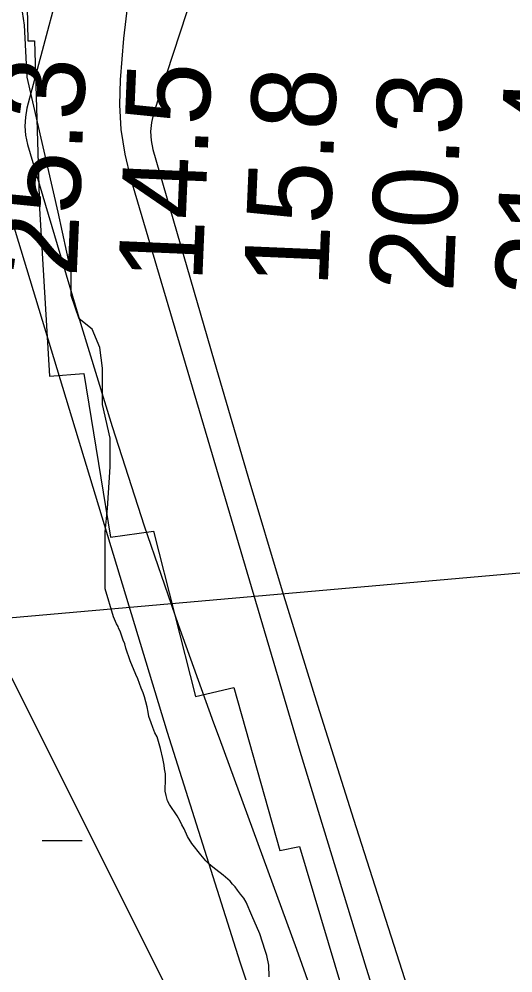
# Model space of a CAD drawing. Extents: x 3281947 to 3319794, y 715894 to 741249.
# Drawn here: x 3294621 to 3295014, y 730771 to 731530 of the extents above; entities that cross this region are included whole.
import ezdxf

# ---------------------------------------------------------------- set-up
doc = ezdxf.new("R2010")
doc.units = 0
for name, color, linetype in [('V-RIVR-RANG', 7, 'Continuous'), ('V-RRAP-RVMT', 7, 'Continuous'), ('V-SITE-VEGE', 7, 'Continuous'), ('V-TOPO-MAJR', 7, 'Continuous'), ('V-TOPO-MINR', 7, 'Continuous'), ('V-WETL-SWMP', 7, 'Continuous')]:
    doc.layers.add(name, color=color, linetype=linetype)

msp = doc.modelspace()

# ---------------------------------------------------------------- linework, layer by layer
at = {"layer": 'V-RIVR-RANG'}
msp.add_line((3294266.87, 731023.3), (3295442.35, 731126.59), dxfattribs=at)
at = {"layer": 'V-RRAP-RVMT'}
for points in [[(3294916.96, 732419.73), (3294695.42, 732452.11), (3294671.83, 732315.84), (3294667.42, 732316.1), (3294647.19, 732175.26), (3294649.39, 732174.71), (3294634, 732052.32), (3294626.51, 732052.13), (3294612.34, 731919.29), (3294603.81, 731919.44), (3294591.01, 731780.63), (3294593.83, 731648.32), (3294624.8, 731648.66), (3294627.58, 731512.85), (3294632.84, 731512.67), (3294636.8, 731379.25), (3294644.88, 731245.94), (3294672.26, 731248.07)], [(3294672.26, 731248.07), (3294693.46, 731117.69), (3294727.56, 731122.49), (3294761.16, 730990.85), (3294791.42, 730997.99), (3294828.28, 730868.41), (3294843.88, 730871.62), (3294883.31, 730739.23)]]:
    msp.add_lwpolyline(points, dxfattribs=at)
at = {"layer": 'V-SITE-VEGE'}
for points in [[(3294774.73, 730854.96), (3294771.77, 730857.84), (3294769.33, 730860), (3294765.16, 730864.84), (3294758.23, 730873.96), (3294754.79, 730879.49), (3294751.88, 730885.72), (3294750.16, 730888.76), (3294748.8, 730891.78), (3294746.56, 730895.88), (3294740.34, 730904.99), (3294738.8, 730907.85), (3294737.63, 730912.11), (3294736.97, 730915.47), (3294737.13, 730925.55), (3294737.02, 730929.44), (3294736.37, 730933.33), (3294736.07, 730936.34), (3294735.08, 730941.48), (3294733.27, 730949.64), (3294730.41, 730958.7), (3294728.69, 730962.09), (3294727.17, 730966.35), (3294725.64, 730969.91), (3294723.95, 730975.06), (3294723.47, 730978.43), (3294722.66, 730982.69), (3294720.48, 730990.67), (3294719.3, 730993.87), (3294717.77, 730997.61), (3294716.58, 731001.16), (3294715.05, 731005.07), (3294713.52, 731008.46), (3294708.92, 731019.31), (3294705.54, 731029.44), (3294704.71, 731032.81), (3294703.34, 731035.83), (3294702.51, 731038.85), (3294701.32, 731042.05), (3294699.79, 731045.61), (3294699.45, 731046.68), (3294698.25, 731048.81), (3294695.7, 731054.4), (3294689.02, 731076.55), (3294689.02, 731122.03), (3294691.09, 731140.64), (3294693.16, 731173.71), (3294693.16, 731196.45), (3294686.96, 731223.33), (3294686.96, 731252.27), (3294684.89, 731268.81), (3294678.69, 731283.28), (3294668.36, 731291.55), (3294662.16, 731310.16), (3294662.16, 731328.76), (3294651.83, 731376.31), (3294627.03, 731483.81), (3294624.96, 731525.15), (3294620.83, 731552.03)], [(3294819.63, 730767.83), (3294819.52, 730777.04), (3294817.83, 730784.89), (3294816.49, 730788.63), (3294812.3, 730801.99), (3294805.77, 730816.54), (3294801.36, 730827.36), (3294799.44, 730830.36), (3294796.84, 730833.58), (3294794.41, 730836.81), (3294792.69, 730839.31), (3294790.6, 730841.64), (3294788.69, 730843.96), (3294783.11, 730848.65), (3294777.35, 730853.16), (3294774.73, 730854.96)]]:
    msp.add_lwpolyline(points, dxfattribs=at)
at = {"layer": 'V-TOPO-MAJR'}
msp.add_lwpolyline([(3294663.53, 731597.42), (3294626.87, 731459.26), (3294625.58, 731452.02), (3294625.09, 731444.79), (3294625.79, 731437.58), (3294627.29, 731430.38), (3294670.29, 731285.31), (3294694.72, 731205.85), (3294720.2, 731126.73), (3294747.27, 731048.15), (3294775.39, 730969.92), (3294779.82, 730957.97), (3294810.74, 730873.96), (3294841.36, 730789.83), (3294871.55, 730705.55)], dxfattribs=at)
at = {"layer": 'V-TOPO-MINR'}
for points in [[(3294832.29, 731774.83), (3294727.61, 731455), (3294725.97, 731447.86), (3294725.2, 731440.7), (3294725.72, 731433.53), (3294727.11, 731426.33), (3294775.89, 731257.75), (3294802.75, 731166.37), (3294830.11, 731075.14), (3294858.24, 730984.15), (3294886.88, 730893.31), (3295191.59, 729940.72), (3295194.33, 729933.3), (3295197.51, 729926.09), (3295201.32, 729919.21), (3295205.55, 729912.53), (3295403.56, 729629.43), (3295477.46, 729524.23), (3295551.65, 729419.25), (3295626.28, 729314.57), (3295701.2, 729210.11)], [(3294707.9, 731550.8), (3294703.73, 731514.62), (3294701.12, 731481.62), (3294700.65, 731461.8), (3294701.62, 731442.13), (3294704.75, 731422.69), (3294709.31, 731403.39), (3294844.22, 730947.39), (3294896.8, 730774.57), (3294951.13, 730602.32)], [(3294602.79, 731408.53), (3294738.45, 730962.52), (3294796.28, 730779.62), (3294856.74, 730597.62), (3294921.16, 730416.98), (3294988.22, 730237.26), (3295126.3, 729879.17), (3295290.14, 729586.16), (3295311.99, 729547.8), (3295334.22, 729509.66), (3295357.04, 729471.88), (3295380.25, 729434.32), (3295403.87, 729397.01), (3295427.63, 729359.8), (3295451.62, 729322.73), (3295475.76, 729285.75), (3295627.23, 729055.25), (3295637.86, 729035.84), (3295646.29, 729015.71), (3295651.44, 728994.5), (3295654.38, 728972.57), (3295650.33, 728962.98), (3295644.69, 728957.29), (3295639.23, 728957.38)]]:
    msp.add_lwpolyline(points, dxfattribs=at)
at = {"layer": 'V-WETL-SWMP'}
msp.add_line((3294638.91, 730876.41), (3294670.91, 730876.41), dxfattribs=at)
msp.add_lwpolyline([(3297671.2, 727505.47), (3297540.93, 727555.62), (3297430.71, 727645.88), (3297340.52, 727726.1), (3297240.31, 727816.36), (3297110.04, 727886.56), (3296949.71, 727946.73), (3296789.38, 728026.96), (3296488.76, 728187.42), (3296268.31, 728277.68), (3296055.12, 728398.33), (3296025.05, 728504.79), (3295911.72, 728648.29), (3295786.82, 728828.81), (3295637.01, 728979.68), (3295516.76, 729059.91), (3295376.47, 729330.68), (3295316.35, 729491.14), (3295246.2, 729601.45), (3295139.65, 729832.29), (3294819.88, 730595.51), (3294614.9, 731005.45)], dxfattribs=at)

# ---------------------------------------------------------------- texts
at = {"layer": 'V-RIVR-RANG'}
for s, p in [('25.3', (3294666.4, 731324.14)), ('14.5', (3294766.32, 731320.11)), ('15.8', (3294866.24, 731316.09)), ('20.3', (3294966.16, 731312.06)), ('21.4', (3295066.07, 731308.04))]:
    msp.add_text(s, height=67, rotation=87.54833, dxfattribs=at).set_placement(p)

doc.saveas('drawing.dxf')
